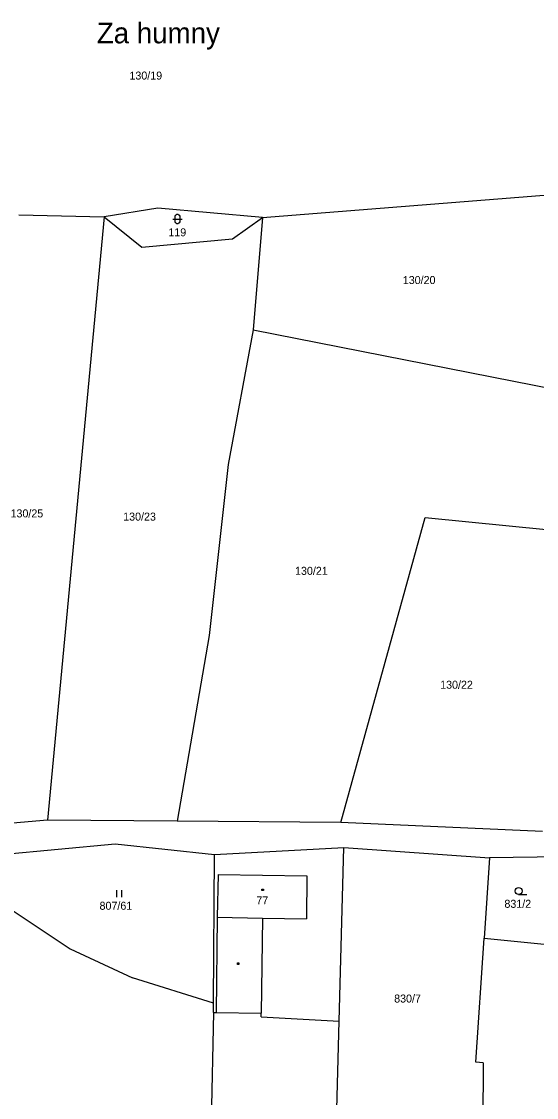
# Model space of a CAD drawing. Extents: x -791032 to -787751, y -1106872 to -1104403.
# Drawn here: x -789685.4 to -789576, y -1105599.2 to -1105370.6 of the extents above; entities that cross this region are included whole.
import ezdxf

# ---------------------------------------------------------------- set-up
doc = ezdxf.new("R2010")
doc.units = 0
for name, color, linetype in [('Vrstva 1', 7, 'Continuous'), ('Vrstva 14', 7, 'Continuous'), ('Vrstva 15', 7, 'Continuous'), ('Vrstva 2', 7, 'Continuous'), ('Vrstva 23', 7, 'Continuous'), ('Vrstva 25', 7, 'Continuous'), ('Vrstva 39', 7, 'Continuous')]:
    doc.layers.add(name, color=color, linetype=linetype)

msp = doc.modelspace()

# ---------------------------------------------------------------- linework, layer by layer
at = {"layer": 'Vrstva 1'}
for p, q in [((-789634.19, -1105412.22), (-789567.47, -1105406.94)), ((-789656.43, -1105410.25), (-789667.88, -1105412.07)), ((-789634.19, -1105412.22), (-789656.43, -1105410.25)), ((-789686.01, -1105411.64), (-789667.88, -1105412.07)), ((-789667.88, -1105412.07), (-789679.89, -1105540.23)), ((-789667.88, -1105412.07), (-789659.86, -1105418.52)), ((-789640.56, -1105416.78), (-789634.19, -1105412.22)), ((-789634.19, -1105412.22), (-789636.17, -1105436.07)), ((-789659.86, -1105418.52), (-789640.56, -1105416.78)), ((-789636.17, -1105436.07), (-789641.49, -1105464.7)), ((-789636.17, -1105436.07), (-789571.77, -1105448.75)), ((-789641.49, -1105464.7), (-789645.51, -1105501.05)), ((-789617.52, -1105540.72), (-789599.62, -1105475.92)), ((-789599.62, -1105475.92), (-789573.18, -1105478.57)), ((-789645.51, -1105501.05), (-789652.33, -1105540.45)), ((-789679.89, -1105540.23), (-789696.75, -1105541.71)), ((-789652.33, -1105540.45), (-789679.89, -1105540.23)), ((-789617.52, -1105540.72), (-789652.33, -1105540.45)), ((-789574.71, -1105542.67), (-789617.52, -1105540.72)), ((-789689.74, -1105547.57), (-789665.5, -1105545.31)), ((-789665.5, -1105545.31), (-789644.36, -1105547.55)), ((-789644.6, -1105579.11), (-789644.36, -1105547.55)), ((-789644.36, -1105547.55), (-789616.9, -1105546.09)), ((-789617.87, -1105582.98), (-789616.9, -1105546.09)), ((-789616.9, -1105546.09), (-789585.93, -1105548.24)), ((-789585.93, -1105548.24), (-789587.07, -1105565.34)), ((-789569.64, -1105548.02), (-789585.93, -1105548.24)), ((-789690.04, -1105557.68), (-789675.05, -1105567.59)), ((-789588.83, -1105591.68), (-789587.07, -1105565.34)), ((-789587.07, -1105565.34), (-789569.75, -1105567.06)), ((-789675.05, -1105567.59), (-789661.82, -1105573.75)), ((-789644.6, -1105579.11), (-789661.82, -1105573.75)), ((-789644.61, -1105581.09), (-789644.6, -1105579.11)), ((-789644.61, -1105581.09), (-789645.89, -1105645.25)), ((-789644.61, -1105581.09), (-789644.01, -1105581.1)), ((-789644.01, -1105581.1), (-789634.48, -1105581.23)), ((-789634.49, -1105582.03), (-789634.48, -1105581.23)), ((-789634.49, -1105582.03), (-789617.87, -1105582.98)), ((-789618.51, -1105607.33), (-789617.87, -1105582.98)), ((-789587.28, -1105591.81), (-789588.83, -1105591.68)), ((-789587.28, -1105591.81), (-789587.42, -1105608.89))]:
    msp.add_line(p, q, dxfattribs=at)
at = {"layer": 'Vrstva 2'}
for p, q in [((-789643.62, -1105551.81), (-789643.81, -1105560.89)), ((-789643.62, -1105551.81), (-789624.76, -1105552.11)), ((-789624.76, -1105552.11), (-789624.87, -1105561.22)), ((-789643.81, -1105560.89), (-789644.01, -1105581.1)), ((-789643.81, -1105560.89), (-789634.2, -1105561.06)), ((-789634.2, -1105561.06), (-789634.48, -1105581.23)), ((-789634.2, -1105561.06), (-789624.87, -1105561.22))]:
    msp.add_line(p, q, dxfattribs=at)
at = {"layer": 'Vrstva 23'}
for p, q in [((-789653.27, -1105412.54), (-789651.27, -1105412.54)), ((-789652.77, -1105411.94), (-789652.67, -1105411.74)), ((-789652.77, -1105413.14), (-789652.77, -1105411.94)), ((-789652.67, -1105411.74), (-789652.57, -1105411.64)), ((-789652.57, -1105411.64), (-789652.37, -1105411.54)), ((-789652.37, -1105411.54), (-789652.17, -1105411.54)), ((-789652.17, -1105411.54), (-789651.97, -1105411.64)), ((-789651.97, -1105411.64), (-789651.87, -1105411.74)), ((-789651.87, -1105411.74), (-789651.77, -1105411.94)), ((-789651.77, -1105411.94), (-789651.77, -1105413.14)), ((-789652.67, -1105413.34), (-789652.77, -1105413.14)), ((-789652.57, -1105413.44), (-789652.67, -1105413.34)), ((-789652.37, -1105413.54), (-789652.57, -1105413.44)), ((-789652.17, -1105413.54), (-789652.37, -1105413.54)), ((-789651.97, -1105413.44), (-789652.17, -1105413.54)), ((-789651.87, -1105413.34), (-789651.97, -1105413.44)), ((-789651.77, -1105413.14), (-789651.87, -1105413.34)), ((-789665.18, -1105556.59), (-789665.18, -1105555.09)), ((-789664.18, -1105555.09), (-789664.18, -1105556.59)), ((-789579.76, -1105556.06), (-789578.01, -1105556.06))]:
    msp.add_line(p, q, dxfattribs=at)
msp.add_circle((-789579.76, -1105555.31), 0.75, dxfattribs=at)
at = {"layer": 'Vrstva 25'}
for p, q in [((-789634.31, -1105554.89), (-789634.01, -1105554.89)), ((-789634.31, -1105555.19), (-789634.31, -1105554.89)), ((-789634.01, -1105555.19), (-789634.31, -1105555.19)), ((-789634.01, -1105554.89), (-789634.01, -1105555.19)), ((-789639.52, -1105570.59), (-789639.22, -1105570.59)), ((-789639.52, -1105570.89), (-789639.52, -1105570.59)), ((-789639.22, -1105570.59), (-789639.22, -1105570.89)), ((-789639.22, -1105570.89), (-789639.52, -1105570.89))]:
    msp.add_line(p, q, dxfattribs=at)

# ---------------------------------------------------------------- texts
at = {"layer": 'Vrstva 14'}
for s, p in [('130/19', (-789662.476, -1105382.91)), ('119', (-789654.203, -1105416.21)), ('130/20', (-789604.371, -1105426.35)), ('130/25', (-789687.748, -1105475.93)), ('130/23', (-789663.802, -1105476.61)), ('130/21', (-789627.275, -1105488.13)), ('130/22', (-789596.432, -1105512.33)), ('807/61', (-789668.829, -1105559.29)), ('831/2', (-789582.773, -1105558.87)), ('830/7', (-789606.206, -1105579))]:
    msp.add_text(s, height=1.7, dxfattribs=at).set_placement(p)
at = {"layer": 'Vrstva 15'}
msp.add_text('77', height=1.7, dxfattribs=at).set_placement((-789635.51, -1105558.17))
at = {"layer": 'Vrstva 39'}
msp.add_text('Za humny', height=4.4, dxfattribs=at).set_placement((-789669.41, -1105375.21))

doc.saveas('drawing.dxf')
